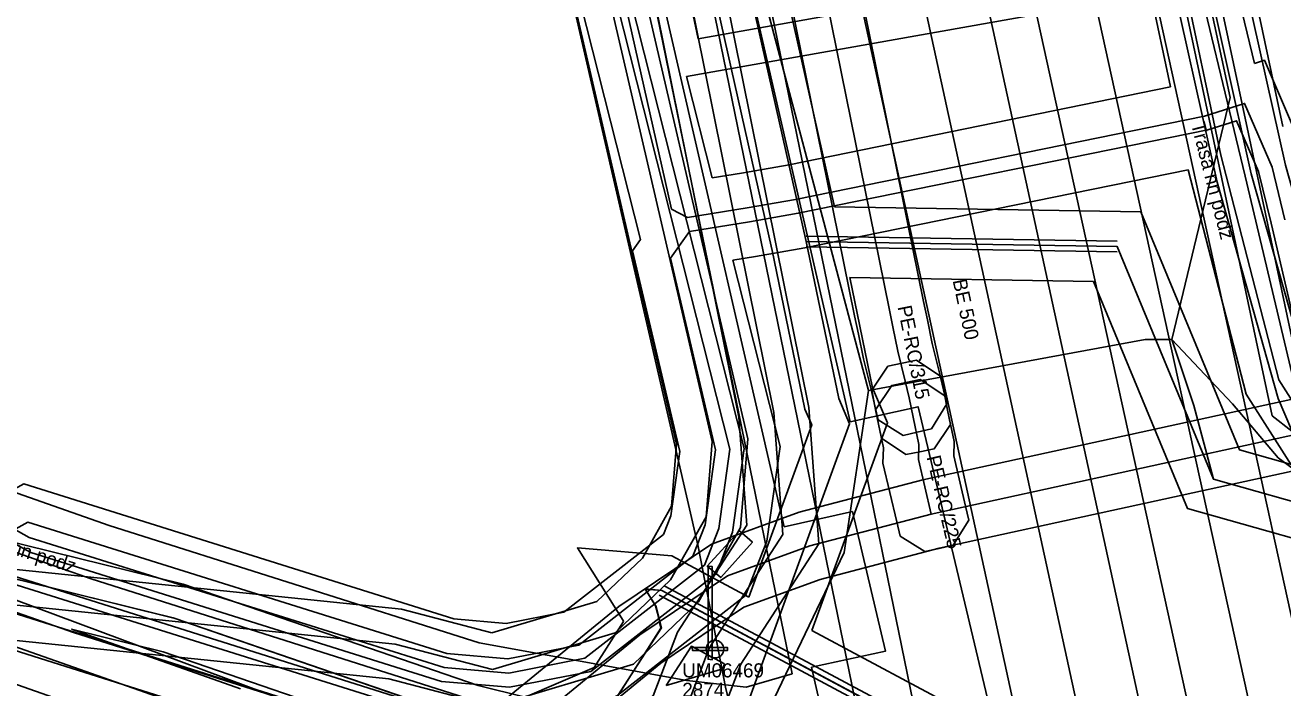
# Model space of a CAD drawing. Extents: x -762993 to -761845, y -975230 to -974501.
# Drawn here: x -762304.94 to -762269.27, y -974984.74 to -974965.94 of the extents above; entities that cross this region are included whole.
import ezdxf

# ---------------------------------------------------------------- set-up
doc = ezdxf.new("R2010")
doc.units = 0
for name, color, linetype in [('IS_CETIN_chranicka', 7, 'Continuous'), ('IS_CETIN_OP', 7, 'Continuous'), ('IS_CETIN_podzem optika zam', 7, 'Continuous'), ('IS_CETIN_podzem out of order', 7, 'Continuous'), ('IS_CEZ-D_anotace', 7, 'Continuous'), ('IS_CEZ-D_el vedeni NN podzem', 7, 'Continuous'), ('IS_CEZ-D_el vedeni VN podzem', 7, 'Continuous'), ('IS_CEZ-D_OP', 7, 'Continuous'), ('IS_CEZ-T_parovod', 7, 'Continuous'), ('IS_CEZ-T_parovod OP', 7, 'Continuous'), ('IS_CRA_podzem telekomunikace', 7, 'Continuous'), ('IS_DPmUL_OP', 7, 'Continuous'), ('IS_DPmUL_trakce anotace', 7, 'Continuous'), ('IS_DPmUL_trakce stozary', 7, 'Continuous'), ('IS_DPmUL_trakce vedeni', 7, 'Continuous'), ('IS_DPmUL_VO lampy', 7, 'Continuous'), ('IS_DPmUL_VO lampy anotace', 7, 'Continuous'), ('IS_DPmUL_VO vedeni podzem', 7, 'Continuous'), ('IS_GASNET_plyn NTL anotace', 7, 'Continuous'), ('IS_GASNET_plyn NTL rad', 7, 'Continuous'), ('IS_GASNET_plyn OP', 7, 'Continuous'), ('IS_SCVK_kanalizace anotace', 7, 'Continuous'), ('IS_SCVK_kanalizace jednotna', 7, 'Continuous'), ('IS_SCVK_kanalizace OP', 7, 'Continuous'), ('IS_SCVK_vodovod OP', 7, 'Continuous'), ('IS_SCVK_vodovod privadec', 7, 'Continuous'), ('IS_T-Mobile_OP', 7, 'Continuous'), ('IS_T-Mobile_podzem optika', 7, 'Continuous')]:
    doc.layers.add(name, color=color, linetype=linetype)

msp = doc.modelspace()

# ---------------------------------------------------------------- linework, layer by layer
at = {"layer": 'IS_CETIN_chranicka'}
for points in [[(-762282.788, -974971.93), (-762273.968, -974972.07)], [(-762282.792, -974972.23), (-762273.972, -974972.37)], [(-762286.961, -974982.112), (-762283.341, -974984.042), (-762274.19, -974988.938), (-762260.571, -974993.605), (-762251.625, -974995.568), (-762242.487, -974996.629)], [(-762286.819, -974981.848), (-762283.199, -974983.778), (-762274.07, -974988.662), (-762260.489, -974993.315), (-762251.575, -974995.272), (-762242.453, -974996.331)]]:
    msp.add_lwpolyline(points, dxfattribs=at)
at = {"layer": 'IS_CETIN_OP'}
msp.add_line((-762303.634, -974983.077), (-762298.838, -974984.767), dxfattribs=at)
for points in [[(-762287.333, -974947.135), (-762285.944, -974953.453), (-762281.987, -974971.093)], [(-762289.287, -974947.565), (-762287.896, -974953.887), (-762283.766, -974972.299)], [(-762332.038, -974969.868), (-762325.973, -974972.002), (-762323.432, -974972.809), (-762321.256, -974973.527), (-762318.954, -974974.571), (-762318.136, -974976.13), (-762306.451, -974980.321), (-762300.467, -974981.8), (-762292.097, -974984.68), (-762290.767, -974985.008), (-762288.807, -974984.163), (-762287.974, -974982.862), (-762287.982, -974982.827), (-762289.282, -974980.773), (-762286.601, -974981.001), (-762284.415, -974982.166)], [(-762281.987, -974971.093), (-762273.297, -974971.231), (-762270.501, -974977.99), (-762261.541, -974980.521), (-762261.009, -974980.205)], [(-762284.415, -974982.166), (-762282.635, -974977.281), (-762282.829, -974976.832), (-762283.769, -974972.282)], [(-762282.633, -974983.117), (-762280.485, -974977.219), (-762280.911, -974976.228), (-762281.558, -974973.1)], [(-762281.558, -974973.1), (-762274.643, -974973.209), (-762271.979, -974979.65), (-762261.259, -974982.679), (-762258.547, -974981.068), (-762252.538, -974987.424), (-762250.848, -974989.451)], [(-762325.112, -974977.633), (-762299.502, -974986.653)], [(-762303.634, -974983.077), (-762301.033, -974983.72), (-762292.941, -974986.505)], [(-762282.633, -974983.117), (-762273.729, -974987.88), (-762260.26, -974992.495), (-762251.435, -974994.432), (-762246.779, -974994.973)], [(-762286.762, -974984.678), (-762286.047, -974983.563), (-762285.106, -974984.064)], [(-762286.762, -974984.678), (-762285.157, -974984.204), (-762285.106, -974984.064)]]:
    msp.add_lwpolyline(points, dxfattribs=at)
at = {"layer": 'IS_CETIN_podzem optika zam'}
for points in [[(-762288.31, -974947.35), (-762286.92, -974953.67), (-762282.79, -974972.08)], [(-762377.62, -974954.57), (-762366.77, -974958.38), (-762363.37, -974959.59), (-762350.74, -974963.98), (-762348.95, -974964.65), (-762339.36, -974968.07), (-762336.01, -974969.53), (-762326.29, -974972.95), (-762323.74, -974973.76), (-762321.62, -974974.46), (-762319.68, -974975.34), (-762318.84, -974976.94), (-762306.74, -974981.28), (-762300.75, -974982.76), (-762292.38, -974985.64), (-762290.68, -974986.06), (-762288.13, -974984.96), (-762286.9, -974983.04), (-762287.05, -974982.43), (-762287.36, -974981.94), (-762286.89, -974981.98), (-762283.27, -974983.91), (-762274.13, -974988.8), (-762260.53, -974993.46)], [(-762299.17, -974985.71), (-762293.22, -974987.63), (-762284.39, -974985.02), (-762281.56, -974977.25), (-762281.87, -974976.53), (-762282.79, -974972.08)], [(-762282.79, -974972.08), (-762273.97, -974972.22), (-762271.24, -974978.82), (-762261.4, -974981.6), (-762258.37, -974979.8), (-762251.79, -974986.76), (-762250.08, -974988.81)], [(-762324.78, -974976.69), (-762299.17, -974985.71)]]:
    msp.add_lwpolyline(points, dxfattribs=at)
at = {"layer": 'IS_CETIN_podzem out of order'}
for points in [[(-762272.42, -974974.86), (-762270.77, -974967.99), (-762273.36, -974955.96), (-762284.91, -974909.78)], [(-762293.19, -974926.11), (-762292.13, -974931.64), (-762291.58, -974936.52), (-762281.02, -974976.31)], [(-762327.23, -974974.06), (-762309.42, -974980.68), (-762296.86, -974985.37), (-762290.2, -974987.41), (-762286.23, -974986.47), (-762283.7, -974985.04), (-762281.71, -974980.9), (-762281.02, -974976.31)], [(-762267.11, -974979.9), (-762269.4, -974978.22), (-762270.7, -974976.68), (-762272.42, -974974.86), (-762273.18, -974974.86), (-762281.02, -974976.31)], [(-762271.8, -974976.73), (-762272.42, -974974.86)], [(-762271.24, -974978.82), (-762271.8, -974976.73)]]:
    msp.add_lwpolyline(points, dxfattribs=at)
at = {"layer": 'IS_CEZ-D_el vedeni NN podzem'}
for points in [[(-762292.054, -974954.011), (-762292.145, -974953.937), (-762291.358, -974953.166), (-762290.951, -974953.062), (-762289.257, -974952.627), (-762288.969, -974952.553), (-762288.196, -974955.224), (-762285.856, -974966.323), (-762272.266, -974963.899), (-762272.118, -974964.474), (-762271.031, -974969.629), (-762269.385, -974976.005), (-762268.341, -974977.635), (-762265.074, -974979.234), (-762262.734, -974979.395), (-762260.132, -974977.413), (-762257.177, -974974.654), (-762254.887, -974973.678), (-762252.67, -974976.58), (-762246.502, -974981.906), (-762245.853, -974981.888), (-762245.113, -974982.66), (-762244.276, -974983.534), (-762244.131, -974983.395)], [(-762394.922, -974961.348), (-762366.691, -974971.325), (-762338.912, -974980.87), (-762333.235, -974982.66), (-762317.369, -974988.815), (-762313.901, -974990.502), (-762312.492, -974990.931), (-762308.55, -974979.749), (-762308.284, -974978.995), (-762308.259, -974979.004), (-762304.782, -974980.906), (-762293.136, -974984.559), (-762291.208, -974984.727), (-762288.899, -974984.279), (-762285.346, -974981.506), (-762284.881, -974980.325), (-762284.547, -974977.953), (-762290.432, -974954.683), (-762291.314, -974953.684), (-762291.816, -974954.174), (-762292.054, -974954.011)], [(-762342.967, -974959.546), (-762342.778, -974959.612), (-762343.206, -974960.852), (-762344.903, -974966.065), (-762333.585, -974970.475), (-762322.985, -974974.011), (-762312.522, -974977.213), (-762309.333, -974978.189), (-762308.125, -974978.628), (-762304.826, -974980.473), (-762293.058, -974984.165), (-762291.229, -974984.323), (-762289.07, -974983.904), (-762285.678, -974981.258), (-762285.27, -974980.222), (-762284.953, -974977.971), (-762290.8, -974954.871), (-762291.335, -974954.264), (-762291.585, -974954.509), (-762292.054, -974954.011)], [(-762272.945, -974957.326), (-762271.974, -974963.424), (-762270.341, -974970.221), (-762269.011, -974975.847), (-762268.064, -974977.325), (-762264.969, -974978.841), (-762262.749, -974978.993), (-762260.312, -974977.034), (-762257.295, -974974.217), (-762254.804, -974973.128), (-762252.371, -974976.312), (-762246.411, -974981.474), (-762245.736, -974981.431), (-762244.85, -974982.356), (-762243.987, -974983.257), (-762244.131, -974983.395)]]:
    msp.add_lwpolyline(points, dxfattribs=at)
at = {"layer": 'IS_CEZ-D_el vedeni VN podzem'}
for points in [[(-762319.41, -974797.73), (-762319.25, -974811.07), (-762319.17, -974818.56), (-762319.75, -974821.12), (-762319.39, -974827.6), (-762319.57, -974829.15), (-762319.18, -974830.57), (-762316.82, -974835.07), (-762316.02, -974837.94), (-762313.42, -974849.63), (-762312.46, -974854.51), (-762310.64, -974863.67), (-762308.7, -974872.87), (-762307.01, -974881.16), (-762305.95, -974886.26), (-762303.49, -974897.19), (-762302.61, -974900), (-762301.21, -974905.67), (-762297.61, -974922.54), (-762294.15, -974938.33), (-762293.77, -974942.53), (-762292.42, -974946.94), (-762291.37, -974950), (-762286.61, -974971.16)], [(-762286.61, -974971.16), (-762286.162, -974971.395), (-762284.464, -974971.122), (-762283.093, -974970.883), (-762271.495, -974968.517), (-762270.357, -974968.16), (-762269.579, -974969.967), (-762269.216, -974971.463)], [(-762322.36, -974987.09), (-762313.05, -974990.27), (-762312.11, -974987.34), (-762310, -974982.03), (-762309.51, -974981.11), (-762307.19, -974981.33), (-762304.87, -974980.04), (-762292.98, -974983.77), (-762291.25, -974983.92), (-762289.24, -974983.53), (-762286.01, -974981.01), (-762285.66, -974980.12), (-762285.36, -974977.99), (-762286.64, -974972.55), (-762286.099, -974971.79), (-762284.398, -974971.517), (-762283.019, -974971.276), (-762271.395, -974968.905), (-762270.582, -974968.65), (-762269.96, -974970.094), (-762269.605, -974971.556), (-762268.637, -974975.689)]]:
    msp.add_lwpolyline(points, dxfattribs=at)
at = {"layer": 'IS_CEZ-D_OP'}
msp.add_line((-762285.459, -974970.269), (-762286.185, -974967.397), dxfattribs=at)
for points in [[(-762287.491, -974972.021), (-762291.572, -974955.896), (-762291.614, -974955.937), (-762292.782, -974954.697)], [(-762271.957, -974957.169), (-762270.993, -974963.228), (-762270.08, -974967.025)], [(-762286.185, -974967.397), (-762273.019, -974965.049), (-762272.461, -974967.693)], [(-762270.08, -974967.025), (-762269.795, -974966.936), (-762268.627, -974969.649), (-762268.243, -974971.231), (-762267.328, -974975.136), (-762266.821, -974975.93), (-762264.493, -974977.069), (-762262.813, -974977.184), (-762261.942, -974977.062)], [(-762285.459, -974970.269), (-762284.629, -974970.136), (-762283.279, -974969.9), (-762272.461, -974967.693)], [(-762285.459, -974970.269), (-762284.629, -974970.136), (-762283.279, -974969.9), (-762272.461, -974967.693)], [(-762284.868, -974972.605), (-762284.233, -974972.503), (-762282.833, -974972.259), (-762271.958, -974970.04)], [(-762271.958, -974970.04), (-762270.313, -974976.41), (-762269.032, -974978.41), (-762265.338, -974980.218), (-762262.427, -974980.418), (-762261.034, -974979.357)], [(-762305.235, -974979.099), (-762304.981, -974978.957), (-762292.785, -974982.783), (-762291.303, -974982.912), (-762289.666, -974982.594), (-762286.841, -974980.39), (-762286.634, -974979.864), (-762286.376, -974978.036), (-762287.717, -974972.339), (-762287.491, -974972.021)], [(-762305.608, -974981.594), (-762305.175, -974981.831), (-762293.331, -974985.546), (-762291.155, -974985.735), (-762288.473, -974985.215), (-762284.516, -974982.126), (-762283.907, -974980.581), (-762283.529, -974977.898), (-762284.868, -974972.605)]]:
    msp.add_lwpolyline(points, dxfattribs=at)
at = {"layer": 'IS_CEZ-T_parovod'}
msp.add_line((-762277.86, -975004.82), (-762282.64, -974984.16), dxfattribs=at)
for points in [[(-762283.42, -974980.17), (-762292.84, -974939.22), (-762294.43, -974931.67), (-762295.16, -974928.19)], [(-762283.42, -974980.17), (-762281.48, -974979.74), (-762280.54, -974983.7), (-762282.64, -974984.16)]]:
    msp.add_lwpolyline(points, dxfattribs=at)
at = {"layer": 'IS_CEZ-T_parovod OP'}
for p in [(-762285.856, -974980.73), (-762280.855, -975002.967)]:
    msp.add_line(p, (-762285.076, -974984.724), dxfattribs=at)
for points in [[(-762285.856, -974980.73), (-762295.282, -974939.758), (-762296.877, -974932.184), (-762297.607, -974928.703)], [(-762281.54, -974977.193), (-762290.398, -974938.682), (-762291.983, -974931.156), (-762292.208, -974930.087)], [(-762281.54, -974977.193), (-762279.616, -974976.766), (-762277.52, -974985.598), (-762279.634, -974986.061)]]:
    msp.add_lwpolyline(points, dxfattribs=at)
at = {"layer": 'IS_CRA_podzem telekomunikace'}
msp.add_line((-762285.899, -974982.508), (-762276.159, -974987.718), dxfattribs=at)
for points in [[(-762286.963, -974982.858), (-762286.915, -974983.05), (-762288.133, -974984.967), (-762290.685, -974986.061), (-762292.389, -974985.635), (-762300.689, -974982.775), (-762306.75, -974981.275), (-762318.851, -974976.949), (-762319.685, -974975.352), (-762321.623, -974974.461), (-762323.743, -974973.764), (-762326.285, -974972.953), (-762335.993, -974969.53), (-762339.363, -974968.07), (-762348.947, -974964.652), (-762363.377, -974959.593), (-762377.637, -974954.573), (-762392.217, -974949.493), (-762417.036, -974940.799), (-762419.044, -974939.84), (-762421.242, -974939.701), (-762425.393, -974938.364)], [(-762286.947, -974982.872), (-762287.061, -974982.418), (-762287.363, -974981.93), (-762286.888, -974981.982), (-762285.899, -974982.508)]]:
    msp.add_lwpolyline(points, dxfattribs=at)
at = {"layer": 'IS_DPmUL_OP'}
for points in [[(-762258.333, -974977.451), (-762258.911, -974976.857), (-762264.915, -974977.224), (-762266.907, -974977.291), (-762267.513, -974975.869), (-762269.198, -974969.908), (-762270.652, -974963.384), (-762273.142, -974952.356), (-762275.203, -974942.951), (-762278.102, -974930.696), (-762280.281, -974920.247), (-762281.475, -974915.132), (-762281.962, -974913.124), (-762282.189, -974912.029), (-762283.754, -974904.594), (-762284.925, -974900.109), (-762286.219, -974894.21), (-762287.471, -974887.789), (-762288.305, -974884.361), (-762293.731, -974861.088), (-762293.932, -974860.117)], [(-762260.681, -974978.969), (-762264.821, -974979.222), (-762268.209, -974979.335), (-762269.403, -974976.537), (-762271.138, -974970.398), (-762272.604, -974963.822), (-762275.094, -974952.79), (-762277.153, -974943.395), (-762280.054, -974931.13), (-762282.235, -974920.679), (-762283.421, -974915.594), (-762283.914, -974913.562), (-762284.147, -974912.437), (-762285.702, -974905.052), (-762286.871, -974900.577), (-762288.177, -974894.616), (-762289.425, -974888.217), (-762290.251, -974884.825), (-762295.685, -974861.518), (-762295.891, -974860.523)], [(-762289.08, -974945.211), (-762282.713, -974976.79), (-762282.434, -974980.657), (-762284.649, -974984.068)], [(-762291.032, -974945.653), (-762284.699, -974977.06), (-762284.478, -974980.131), (-762286.443, -974983.158)], [(-762286.443, -974983.158), (-762287.13, -974984.968), (-762288.483, -974985.833), (-762292.533, -974985.594), (-762306.491, -974981.186)], [(-762284.649, -974984.068), (-762285.496, -974986.296), (-762287.953, -974987.867), (-762292.899, -974987.576), (-762307.093, -974983.094)]]:
    msp.add_lwpolyline(points, dxfattribs=at)
at = {"layer": 'IS_DPmUL_trakce stozary'}
msp.add_circle((-762285.378, -974983.643), 0.25, dxfattribs=at)
at = {"layer": 'IS_DPmUL_trakce vedeni'}
msp.add_lwpolyline([(-762245.348, -974993.683), (-762251.428, -974985.673), (-762257.908, -974979.323), (-762259.308, -974977.883), (-762264.868, -974978.223), (-762267.558, -974978.313), (-762268.458, -974976.203), (-762270.168, -974970.153), (-762271.628, -974963.603), (-762274.118, -974952.573), (-762276.178, -974943.173), (-762279.078, -974930.913), (-762281.258, -974920.463), (-762282.448, -974915.363), (-762282.938, -974913.343), (-762283.168, -974912.233), (-762284.728, -974904.823), (-762285.898, -974900.343), (-762287.198, -974894.413), (-762288.448, -974888.003), (-762289.278, -974884.593), (-762294.708, -974861.303), (-762294.911, -974860.32)], dxfattribs=at)
at = {"layer": 'IS_DPmUL_VO lampy'}
for points in [[(-762284.686, -974980.283), (-762284.316, -974980.613), (-762285.216, -974981.613), (-762285.596, -974981.293)], [(-762285.576, -974981.293), (-762285.456, -974981.303), (-762285.456, -974983.943), (-762285.576, -974983.933)], [(-762286.026, -974983.593), (-762285.026, -974983.593), (-762285.026, -974983.683), (-762286.016, -974983.683)]]:
    msp.add_lwpolyline(points, close=True, dxfattribs=at)
at = {"layer": 'IS_DPmUL_VO vedeni podzem'}
for points in [[(-762290.056, -974945.432), (-762283.706, -974976.925), (-762283.456, -974980.394), (-762285.546, -974983.613)], [(-762285.546, -974983.613), (-762286.313, -974985.632), (-762288.218, -974986.85), (-762292.716, -974986.585), (-762306.792, -974982.14)]]:
    msp.add_lwpolyline(points, dxfattribs=at)
at = {"layer": 'IS_GASNET_plyn NTL rad'}
for points in [[(-762295.286, -974903.832), (-762295.02, -974905.04), (-762289.42, -974930.22), (-762287.08, -974941.19), (-762280.44, -974973.98), (-762280.33, -974974.5), (-762280.19, -974975.19), (-762279.98, -974976.04), (-762279.87, -974976.51)], [(-762279.76, -974977.06), (-762279.87, -974976.51)], [(-762279.25, -974979.81), (-762279.61, -974978.26), (-762279.6, -974977.84), (-762279.76, -974977.06)], [(-762268.53, -974977.47), (-762279.25, -974979.81), (-762282.69, -974980.71), (-762285.02, -974981.56), (-762287.51, -974983.24), (-762290.82, -974985.95), (-762296.31, -974990.87), (-762297.73, -974991.97), (-762298.54, -974992.86), (-762298.88, -974993.2), (-762299.23, -974993.53)]]:
    msp.add_lwpolyline(points, dxfattribs=at)
at = {"layer": 'IS_GASNET_plyn OP'}
for points in [[(-762295.996, -974905.256), (-762296.27, -974904.012), (-762294.302, -974903.652), (-762294.044, -974904.824), (-762288.443, -974930.007), (-762286.101, -974940.986), (-762279.461, -974973.777), (-762279.351, -974974.297), (-762279.214, -974974.971), (-762279.008, -974975.806), (-762278.896, -974976.282), (-762278.802, -974976.685), (-762279.239, -974977.39), (-762279.642, -974977.484), (-762280.045, -974977.578), (-762280.75, -974977.141), (-762280.844, -974976.738), (-762280.952, -974976.274), (-762281.166, -974975.409), (-762281.309, -974974.703), (-762281.419, -974974.183), (-762288.059, -974941.394), (-762290.397, -974930.433)], [(-762280.659, -974977.662), (-762280.741, -974977.256), (-762280.851, -974976.706), (-762280.932, -974976.3), (-762280.472, -974975.611), (-762280.066, -974975.529), (-762279.66, -974975.448), (-762278.971, -974975.908), (-762278.889, -974976.314), (-762278.779, -974976.864), (-762278.698, -974977.27), (-762279.158, -974977.959), (-762279.564, -974978.041), (-762279.97, -974978.122)], [(-762280.13, -974980.439), (-762280.224, -974980.036), (-762280.613, -974978.363), (-762280.602, -974977.93), (-762280.74, -974977.261), (-762280.823, -974976.855), (-762280.367, -974976.163), (-762279.961, -974976.08), (-762279.555, -974975.997), (-762278.863, -974976.453), (-762278.78, -974976.859), (-762278.598, -974977.75), (-762278.607, -974978.157), (-762278.276, -974979.584), (-762278.182, -974979.987), (-762278.621, -974980.69), (-762279.024, -974980.784), (-762279.427, -974980.878)]]:
    msp.add_lwpolyline(points, close=True, dxfattribs=at)
for points in [[(-762291.471, -974985.19), (-762288.108, -974982.437), (-762285.478, -974980.663), (-762282.989, -974979.754), (-762279.483, -974978.837), (-762268.743, -974976.493)], [(-762268.788, -974978.55), (-762279.017, -974980.783), (-762282.391, -974981.666), (-762284.562, -974982.457), (-762286.912, -974984.043), (-762290.169, -974986.71)]]:
    msp.add_lwpolyline(points, dxfattribs=at)
at = {"layer": 'IS_SCVK_kanalizace jednotna'}
msp.add_lwpolyline([(-762272.009, -974999.487), (-762282.203, -974952.631)], dxfattribs=at)
at = {"layer": 'IS_SCVK_kanalizace OP'}
for points in [[(-762270.299, -974999.115), (-762280.493, -974952.259)], [(-762273.719, -974999.859), (-762283.913, -974953.003)]]:
    msp.add_lwpolyline(points, dxfattribs=at)
at = {"layer": 'IS_SCVK_vodovod OP'}
for points in [[(-762293.748, -974916.96), (-762291.431, -974928.152), (-762279.692, -974985.479)], [(-762296.882, -974917.608), (-762294.565, -974928.798), (-762283.191, -974984.34)], [(-762282.833, -974917.58), (-762281.112, -974927.652), (-762268.54, -974984.934)], [(-762286.185, -974918.152), (-762284.45, -974928.304), (-762271.86, -974985.662)], [(-762370.788, -974956.301), (-762365.679, -974958.103), (-762364.905, -974958.37), (-762350.036, -974963.625), (-762347.061, -974964.615), (-762327.066, -974971.647), (-762323.688, -974972.721), (-762321.219, -974973.584), (-762302.563, -974980.135), (-762292.067, -974983.465), (-762286.179, -974984.538), (-762284.497, -974984.727), (-762283.191, -974984.34)], [(-762371.852, -974959.319), (-762366.733, -974961.125), (-762365.959, -974961.392), (-762351.074, -974966.651), (-762348.097, -974967.643), (-762328.082, -974974.681), (-762324.702, -974975.757), (-762322.277, -974976.604), (-762303.577, -974983.171), (-762292.841, -974986.577), (-762286.645, -974987.706), (-762284.209, -974987.979), (-762282.49, -974987.47)]]:
    msp.add_lwpolyline(points, dxfattribs=at)
at = {"layer": 'IS_SCVK_vodovod privadec'}
for points in [[(-762295.315, -974917.284), (-762292.998, -974928.475), (-762281.41, -974985.064)], [(-762284.509, -974917.866), (-762282.781, -974927.978), (-762270.2, -974985.298)], [(-762371.32, -974957.81), (-762366.206, -974959.614), (-762365.432, -974959.881), (-762350.555, -974965.138), (-762347.579, -974966.129), (-762327.574, -974973.164), (-762324.195, -974974.239), (-762321.748, -974975.094), (-762303.07, -974981.653), (-762292.454, -974985.021), (-762286.412, -974986.122), (-762284.353, -974986.353), (-762281.669, -974985.558)]]:
    msp.add_lwpolyline(points, dxfattribs=at)
at = {"layer": 'IS_T-Mobile_OP'}
for p, q in [((-762288.456, -974960.394), (-762284.451, -974977.675)), ((-762290.404, -974960.846), (-762286.469, -974977.825)), ((-762269.573, -974977.022), (-762271.228, -974969.228)), ((-762265.454, -974980.263), (-762269.573, -974977.022)), ((-762286.469, -974977.825), (-762286.609, -974979.591)), ((-762284.451, -974977.675), (-762284.651, -974980.189)), ((-762286.609, -974979.591), (-762287.438, -974981.059)), ((-762284.651, -974980.189), (-762285.842, -974982.301)), ((-762287.438, -974981.059), (-762288.727, -974982.291)), ((-762294.271, -974982.513), (-762307.637, -974981.137)), ((-762288.727, -974982.291), (-762291.707, -974983.182)), ((-762285.842, -974982.301), (-762287.693, -974984.069)), ((-762291.707, -974983.182), (-762294.271, -974982.513)), ((-762294.627, -974984.487), (-762308.063, -974983.103)), ((-762287.693, -974984.069), (-762291.671, -974985.258)), ((-762291.671, -974985.258), (-762294.627, -974984.487))]:
    msp.add_line(p, q, dxfattribs=at)
for points in [[(-762269.272, -974968.812), (-762272.122, -974955.412)], [(-762271.228, -974969.228), (-762274.078, -974955.828)]]:
    msp.add_lwpolyline(points, dxfattribs=at)
at = {"layer": 'IS_T-Mobile_podzem optika'}
for points in [[(-762270.25, -974969.02), (-762273.1, -974955.62)], [(-762270.25, -974969.02), (-762273.1, -974955.62)], [(-762289.43, -974960.62), (-762285.46, -974977.75)], [(-762289.43, -974960.62), (-762285.46, -974977.75)], [(-762268.67, -974976.46), (-762270.25, -974969.02)], [(-762268.67, -974976.46), (-762270.25, -974969.02)], [(-762285.46, -974977.75), (-762285.63, -974979.89)], [(-762285.46, -974977.75), (-762285.63, -974979.89)], [(-762285.63, -974979.89), (-762286.64, -974981.68)], [(-762285.63, -974979.89), (-762286.64, -974981.68)], [(-762286.64, -974981.68), (-762288.21, -974983.18)], [(-762286.64, -974981.68), (-762288.21, -974983.18)], [(-762294.449, -974983.5), (-762307.85, -974982.12)], [(-762294.449, -974983.5), (-762307.85, -974982.12)], [(-762288.21, -974983.18), (-762291.689, -974984.22)], [(-762288.21, -974983.18), (-762291.689, -974984.22)], [(-762291.689, -974984.22), (-762294.449, -974983.5)], [(-762291.689, -974984.22), (-762294.449, -974983.5)]]:
    msp.add_lwpolyline(points, dxfattribs=at)

# ---------------------------------------------------------------- texts
at = {"layer": 'IS_CEZ-D_anotace'}
for rotation, p in [(284.4752, (-762271.879, -974968.745)), (342.5817, (-762306.832, -974980.472))]:
    msp.add_text('Trasa nn podz', height=0.4, rotation=rotation, dxfattribs=at).set_placement(p)
at = {"layer": 'IS_DPmUL_trakce anotace'}
msp.add_text('2874', height=0.4, dxfattribs=at).set_placement((-762286.306, -974984.999))
at = {"layer": 'IS_DPmUL_VO lampy anotace'}
msp.add_text('UM06469', height=0.4, dxfattribs=at).set_placement((-762286.307, -974984.446))
at = {"layer": 'IS_GASNET_plyn NTL anotace'}
for s, rotation, p in [('PE-RC/315', 281.3099, (-762280.202, -974973.931)), ('PE-RC/225', 283.0756, (-762279.379, -974978.194))]:
    msp.add_text(s, height=0.4, rotation=rotation, dxfattribs=at).set_placement(p)
at = {"layer": 'IS_SCVK_kanalizace anotace'}
msp.add_text('BE 500', height=0.4, rotation=282, dxfattribs=at).set_placement((-762278.64, -974973.184))

doc.saveas('drawing.dxf')
